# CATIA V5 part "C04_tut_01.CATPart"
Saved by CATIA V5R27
Part number: Part1
Material "Copper": density 8900 kg/m3, Young's modulus 1.1e+11 Pa, Poisson ratio 0.33, thermal expansion 1.65e-05 1/K
Bounding box of the stored display mesh (mm): x -99.978 to 99.978, y -99.983 to 99.983, z 0 to 140
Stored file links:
  E:\_Deepak\2017_Deepak\CATIA\Resources\Tutorial Files\Tutorials\c04_catia_v5_6r2016_tut\C04_tut_01.CATPart
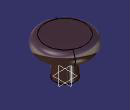
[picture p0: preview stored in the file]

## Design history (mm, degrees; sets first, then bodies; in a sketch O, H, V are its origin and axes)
Body1 (main body), material "Copper"
  Sketch1 on yz-plane, origin (0, 0, 0), H (0, 1, 0), V (0, 0, 1)
    line L1 (0, 0) -> (0, 140)
    line L2 (0, 140) -> (75, 140)
    arc A1 centre (75, 115) radius 25 from (75, 140) to (75, 90) cw
    point P3 (75, 115)
    line L3 (0, 0) -> (40, 0)
    line L4 (40, 0) -> (40, 70)
    line L5 (60, 90) -> (75, 90)
    arc A2 centre (60, 70) radius 20 from (40, 70) to (60, 90) cw
    radius A2 = 20
    distance L3 L2 = 140
    radius A1 = 25
    distance L4 L1 = 40
    distance P3 L1 = 75
    vertical: L1 V, L4 V
    horizontal: L2 H, L3 H, L5 H
    tangency: A1 L2, L5 A1, A2 L4, A2 L5
  Shaft1: profile Sketch1, axis Sketch1.L1, angle 360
